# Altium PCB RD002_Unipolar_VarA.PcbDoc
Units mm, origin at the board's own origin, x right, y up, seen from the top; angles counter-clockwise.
Board outline 27 x 14 mm, 4 copper layers (Top Layer, Int1, Int2, Bottom Layer), stack 1.456 mm thick; 29 components, 15 nets, 67 pads, 34 vias.
Unrouted connection lines stored in the file: 1.
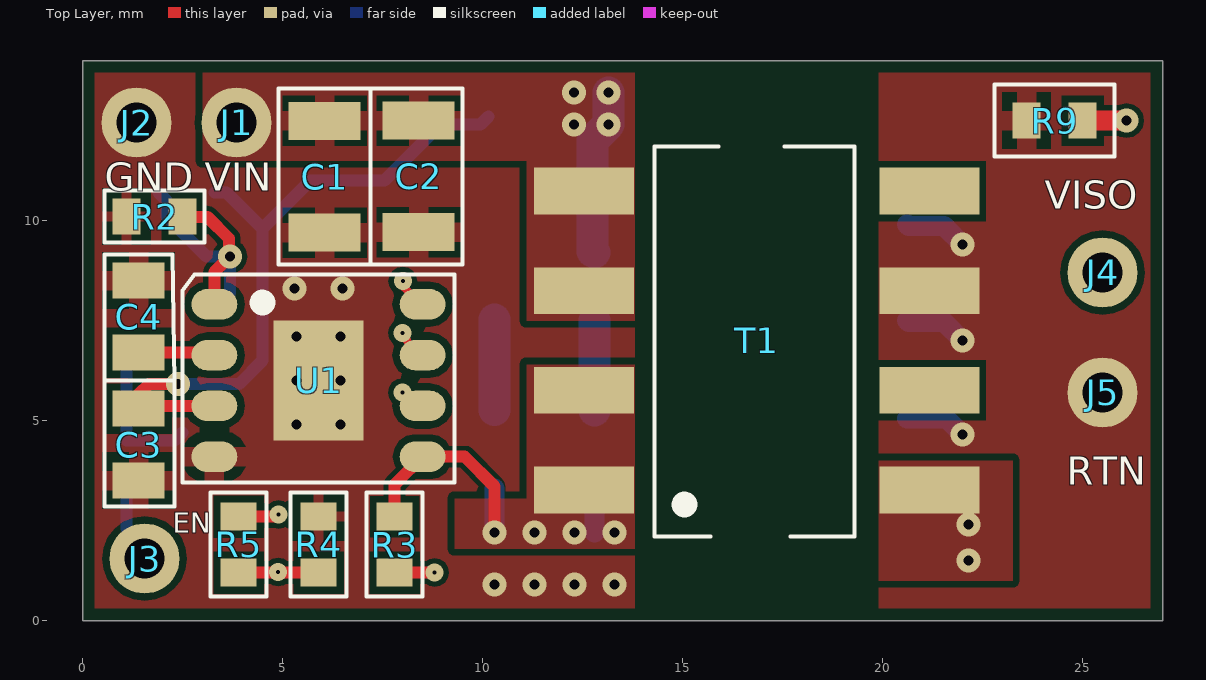
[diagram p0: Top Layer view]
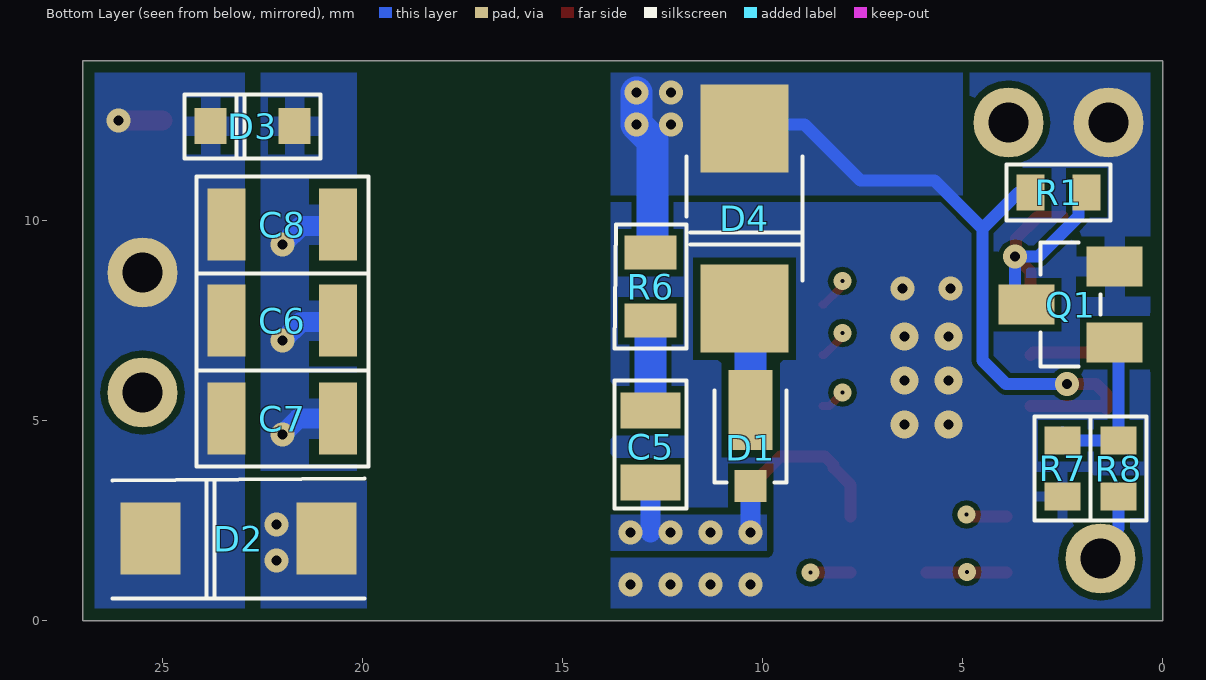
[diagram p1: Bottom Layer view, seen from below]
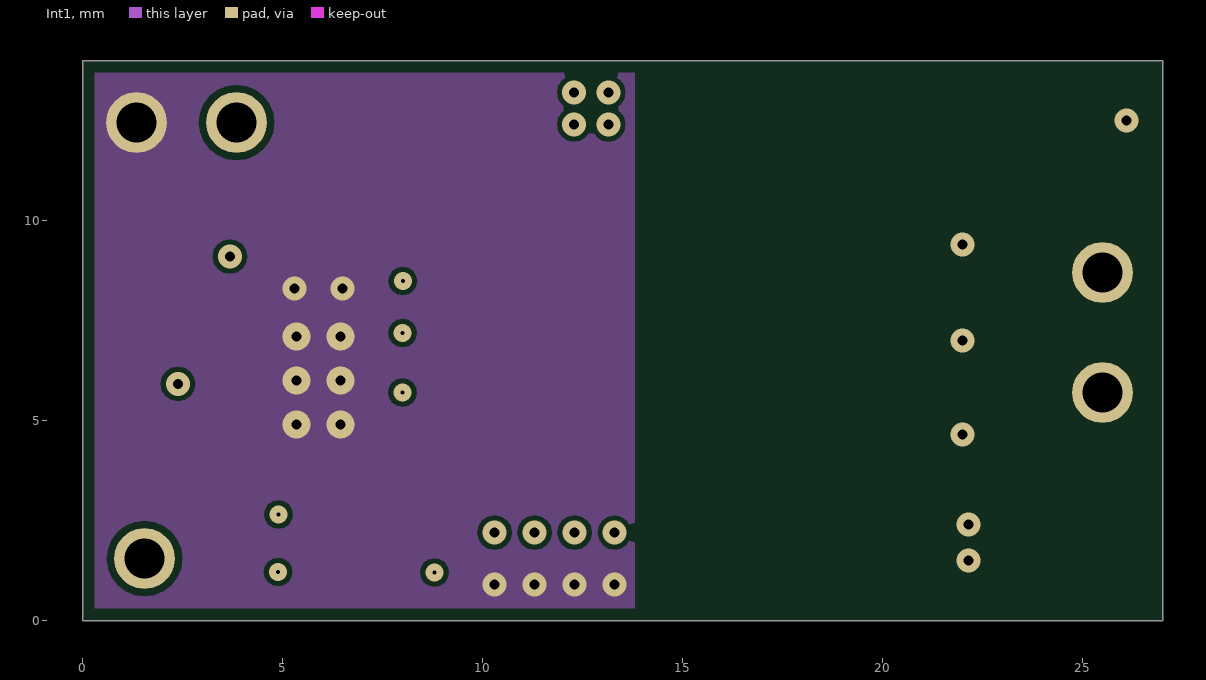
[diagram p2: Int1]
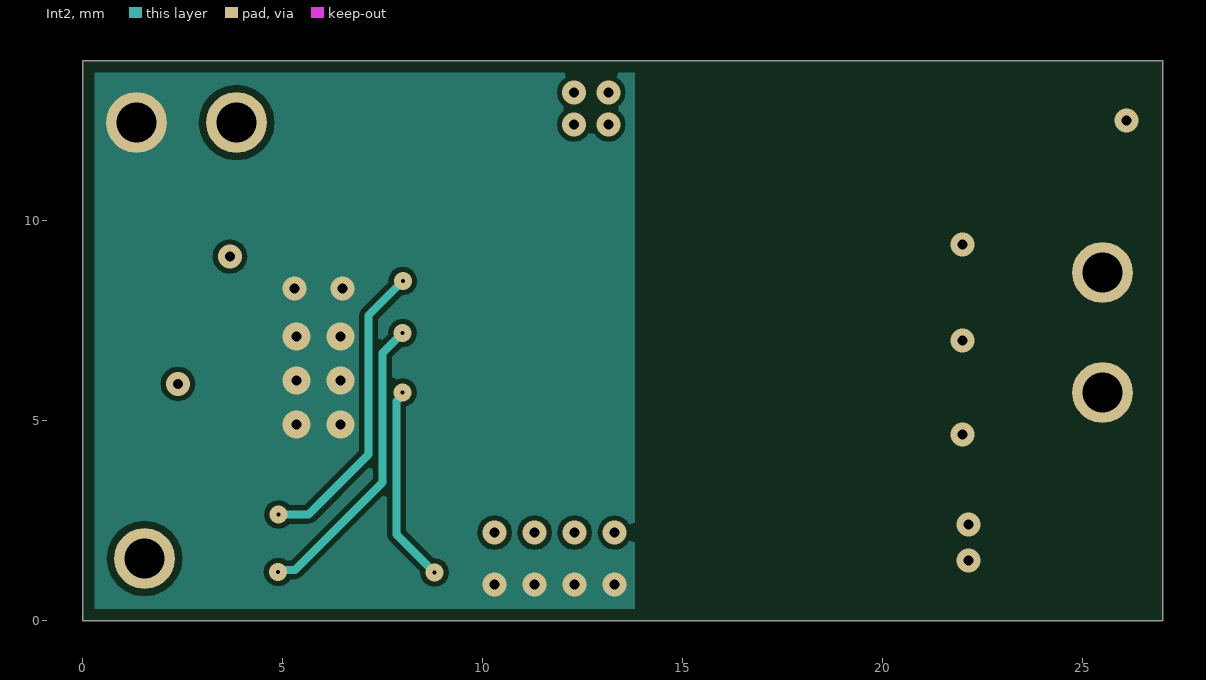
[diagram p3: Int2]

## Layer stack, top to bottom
Top Solder: solder mask 0.0254, SM-001, Dk 4
Top Layer: signal copper 0.035
Dielectric 1: prepreg 0.1067, PP-014, Dk 4.2
Dielectric 2: prepreg 0.1067, PP-014, Dk 4.2
Int1: signal copper 0.035
Dielectric2: core 0.889, Core-041, Dk 4.8
Int2: signal copper 0.0356
Dielectric3: prepreg 0.1067, PP-014, Dk 4.2
Dielectric 3: prepreg 0.1067, PP-014, Dk 4.2
Bottom Layer: signal copper 0.035
Bottom Solder: solder mask 0.0254, SM-001, Dk 4

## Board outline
0,0 27,0 27,14 0,14

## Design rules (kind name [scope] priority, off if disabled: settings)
AcuteAngle [All] p1: minimum=9.00000000000000E+0001 checktracksonly=TRUE
BoardOutlineClearance [All] p1: gap=0.3 ignorepadtopadclearanceinfootprint=FALSE
Clearance Clearance-WE_125um [All] p1: gap=0.175 ignorepadtopadclearanceinfootprint=FALSE except(0.125: Arc-Arc Arc-Track Arc-SMDPad Arc-THPad Arc-Via Arc-Fill Arc-Poly Arc-Region Arc-Text Arc-Hole Track-Track Track-SMDPad Track-THPad Track-Via Track-Fill Track-Poly Track-Region Track-Text Track-Hole Via-Via Via-Fill Via-Poly Via-Region Via-Text Via-Hole)
ComponentClearance [All] p1: gap=0.1 collisioncheckmode=3 verticalgap=0.2 showdistances=FALSE
HoleSize [All] p1: absolutevalues=TRUE maxlimit=10 minlimit=0.02 maxpercent=80.000 minpercent=20.000
HoleToHoleClearance [All] p1: gap=0.6 allowstackedmicrovias=TRUE
MinimumAnnularRing [IsVia] p1: minimumring=0.17
PlaneClearance [All] p1: clearance=0.5
PlaneConnect [All] p1: planeconnectstyle=Relief reliefexpansion=0.508 reliefentries=4 reliefconductorwidth=0.8 reliefairgap=0.254
PolygonConnect PolygonConnect_3 [All vs IsNamedPolygon('VIN_TOP')] p1: connectstyle=Direct reliefconductorwidth=0.254 reliefentries=4 polygonreliefangle="90 Angle" airgapwidth=0.254
PolygonConnect PolygonConnect_2 [All vs IsNamedPolygon('VIN_TOP')] p2: connectstyle=Direct reliefconductorwidth=0.254 reliefentries=4 polygonreliefangle="90 Angle" airgapwidth=0.254
PolygonConnect PolygonConnect_1 [All vs IsNamedPolygon('Top Layer-VIN')] p3: thpad.connectstyle=Relief thpad.reliefconductorwidth=0.254 thpad.reliefentries=4 thpad.polygonreliefangle="90 Angle" thpad.airgapwidth=0.254 smdpad.connectstyle=Direct smdpad.reliefconductorwidth=0.254 smdpad.reliefentries=4 smdpad.polygonreliefangle="90 Angle" smdpad.airgapwidth=0.254 via.connectstyle=Direct via.reliefconductorwidth=0.254 via.reliefentries=4 via.polygonreliefangle="90 Angle" via.airgapwidth=0.254
PolygonConnect [All] p4: connectstyle=Relief reliefconductorwidth=0.5 reliefentries=4 polygonreliefangle="90 Angle" airgapwidth=0.254
RoutingVias [All] p1: holewidth=0.3 width=0.8 viastyle="Through Hole" minholewidth=0.2 minwidth=0.6 maxholewidth=0.4 maxwidth=0.8
SolderMaskExpansion [All] p1: expansion=0.1 istentingtop=FALSE
UnConnectedPin [All] p1:
UnRoutedNet [All] p1: checkbadconnections=TRUE
Width [All] p1: maxlimit=10 minlimit=0.125 preferedwidth=0.3 minimp=50.000000 maximp=50.000000 favimp=50.000000
24 further rules are at their usual default settings.

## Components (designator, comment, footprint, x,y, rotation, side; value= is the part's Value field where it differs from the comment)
C1 "885012108022" C1206 6.05,11.1 r270 top value=10u
C2 "885012108022" C1206 8.4,11.1 r90 top value=10u
C3 "885012207103" C0805#1 1.4,4.4 r90 top value=1u
C4 "885012207103" C0805#1 1.4,7.6 r270 top value=1u
C5 "885012207084" C0805#2 12.8,4.35 r90 bottom value=470p
C6 "885012108022" C1206 22,7.5 r0 bottom value=10u
C7 "885012108022" C1206 22,5.05 r0 bottom value=10u
C8 "885012108022" C1206 22,9.9 r0 bottom value=10u
D1 "V1PM10-M3" D_DO-219AD_(uSMP) 10.3,4.5 r270 bottom
D2 "VSSAF3M10-M3" D_DO-221AC_(SMA_Slim) 23.1,2.05 r0 bottom
D3 "PLZ16BG3H" D_DO-219AC_(uSMF) 22.75,12.35 r0 bottom
D4 "BZG03C27-M3" D_DO-214AC_(SMA) 10.45,10.05 r270 bottom
J1 "Pin_hole_1mm" J_PIN-TH-ROUND-1MM#1 3.85,12.45 r90 top
J2 "Pin_hole_1mm" J_PIN-TH-ROUND-1MM#1 1.35,12.45 r90 top
J3 "Pin_hole_1mm" J_PIN-TH-ROUND-1MM#1 1.55,1.55 r90 top
J4 "Pin_hole_1mm" J_PIN-TH-ROUND-1MM#2 25.75,9.15 r90 top
J5 "Pin_hole_1mm" J_PIN-TH-ROUND-1MM#3 25.8,5.7 r90 top
Q1 "SQ2318AES-T1_BE3" IC_SOT23-3_V 2.3,7.9 r0 bottom
R1 "RC0603FR-07806KL" R0603 2.6,10.7 r0 bottom value=806k
R2 "RC0603FR-07232KL" R0603 1.8,10.1 r0 top value=232k
R3 "RT0603FRE0771K5L" R0603 7.8,1.9 r90 top value=71.5k
R4 "RT0603BRD0710KL" R0603 5.9,1.9 r270 top value=10k
R5 "R0603_DNP" R0603_DNP 3.9,1.9 r270 top value=DNP
R6 "CMP0805-FX-1000ELF" R0805 12.8,8.35 r90 bottom value=100
R7 "RC0603FR-0710KL" R0603 2.5,3.8 r90 bottom value=10k
R8 "RC0603FR-073R3L" R0603 1.1,3.8 r90 bottom value=3.3
R9 "R0603_DNP" R0603_DNP 24.3,12.5 r0 top value=DNP
T1 "750318114" EP7_Extended_Rail 16.85,7 r0 top
U1 "LT8302HS8E#WPBF" LT-S8E-8_V 5.9,6 r0 top

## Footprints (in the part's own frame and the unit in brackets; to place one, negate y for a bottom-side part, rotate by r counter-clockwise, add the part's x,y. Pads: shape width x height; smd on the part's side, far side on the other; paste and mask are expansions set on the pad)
C0805#1 [mm] "Chip Capacitor, 2-Leads, Body 2.00x1.25mm, IPC Low Density"
  rect 0.9x1.3 smd: 1(-0.9,0) 2(0.9,0)
  body extent -1.1,-0.72 1.1,0.72, height 1.45
C0805#2 [mm] "Chip Capacitor, 2-Leads, Body 2.00x1.25mm, IPC Low Density"
  rect 0.9x1.5 smd: 1(-0.9,0) 2(0.9,0)
  body extent -1.1,-0.72 1.1,0.72, height 1.45
C1206 [mm]
  rect 0.95x1.8 smd: 1(-1.39,0) 2(1.4,0)
  body extent -1.7,-0.9 1.7,0.9, height 1.8
D_DO-214AC_(SMA) [mm] "DO-214AC SMA"
  rect 2.2x2.21 smd paste+0 mask+0: A(-2.25,0) C(2.25,0)
  body extent -2.6,-1.28 2.6,1.28, height 2.3
D_DO-219AC_(uSMF) [mm]
  rect 0.8x0.9 smd: A(-1.05,-0.01) C(1.05,-0.01)
  body extent -1.26,-0.66 1.24,0.64, height 0.6
D_DO-219AD_(uSMP) [mil]
  rect 31.5x31.5 smd: A(44.8,0)
  rect 78.74x43.31 smd: C(-30,0)
  body extent -53,-26 45,26, height 29
D_DO-221AC_(SMA_Slim) [mm] "2-Leads, Body 4.2x2.6mm"
  rect 1.5x1.8 smd: A(-2.2,0) C(2.2,0)
  body extent -2.55,-1.3 2.55,1.3, height 1.1
EP7_Extended_Rail [mm] "SMD, 8-Leads, Body 9.8x7.0mm (max), Pitch 2.49mm, IPC Medium Density"
  rect 2.5x1.17 smd: 1(-4.31,-3.735) 2(-4.31,-1.245) 3(-4.31,1.245) 4(-4.31,3.735) 5(4.32,3.735) 6(4.32,1.245) 7(4.32,-1.245) 8(4.32,-3.735)
  body extent -5.06,-5.65 5.04,5.45, height 11.39
IC_SOT23-3_V [mm] "SOT23, 3-Leads, Body 3.12x1.5mm, Pitch 0.95mm"
  rect 1.4x1 smd: 1(-1.1,0.95) 2(-1.1,-0.95) 3(1.1,0)
  body extent -1.35,-1.56 1.35,1.56, height 1.2
J_PIN-TH-ROUND-1MM#1 [mm] "PIN-TH-ROUND-1MM"
  round 1.75 / inner round 1.524 / far side round 1.75 hole 1: 1(0,0)
J_PIN-TH-ROUND-1MM#2 [mm] "PIN-TH-ROUND-1MM"
  round 1.75 / inner round 1.524 / far side round 1.75 hole 1: 1(-0.45,0.25)
J_PIN-TH-ROUND-1MM#3 [mm] "PIN-TH-ROUND-1MM"
  round 1.75 / inner round 1.524 / far side round 1.75 hole 1: 1(0,0.3)
LT-S8E-8_V [mm] "SOIC, 8-Leads, Body 4.9x3.9mm, Pitch 1.27mm, Thermal Pad 3.25x2.26mm, Recommended"
  oval 1.143x0.76 smd: 1(-2.602,1.905) 2(-2.602,0.635) 3(-2.602,-0.635) 4(-2.602,-1.905) 5(2.601,-1.905) 6(2.601,-0.635) 7(2.601,0.635) 8(2.601,1.905)
  rect 2.26x2.99 smd paste-5: 9(0,0)
  body extent -3.01,-2.45 3.01,2.45, height 1.75
R0603 [mm] "Chip Resistor, Body 1.6x0.8mm, IPC High Density"
  rect 0.7x0.9 smd: 1(-0.7,0) 2(0.7,0)
  body extent -0.85,-0.47 0.85,0.47, height 0.6
R0603_DNP [mm] "Chip Resistor, Body 1.6x0.8mm, IPC High Density"
  rect 0.7x0.9 smd: 1(-0.7,0) 2(0.7,0)
R0805 [mm] "Chip Resistor, Body 2.0x1.3mm, IPC High Density"
  rect 0.85x1.3 smd: 1(-0.85,0) 2(0.85,0)
  body extent -1.1,-0.67 1.1,0.68, height 0.7

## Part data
C1 C2 C6 C7 C8: "MLCC 10uF 50V 10% X7R 1206 General Purpose", MFR="Wurth Elektronik", Package=1206, Voltage=50V
C3 C4: "MLCC 1uF 50V 10% X7R 0805 General Purpose", DC-Voltage=50V, Dielectric=X7R, MFR="Wurth Elektronik", Package=0805, Tolerance=10%
C5: "MLCC SMD 470p 50V 10% X7R 0805 General Purpose", MFR="Wurth Elektronik"
D1: "Schottky Rectifier 1A 100V SMD DO-219AD (uSMP) V1PM10-M3", Current=1A, MFR=Vishay, Package="DO-219AD (uSMP)", Voltage=100V
D2: "Schottky Rectifier 3A 100V SMD DO-221AC (SMA_Slim) VSSAF3M10-M3", Current=3A, MFR=Vishay, Package="DO-221AC (SMA Slim)", Voltage=100V
D3: "Zener 16V 0.5W SMD DO-219AC (uSMF) PLZ16BG3H", MFR=Vishay, Package="DO-219AC (uSMF)", Power=0.5W, Voltage=16V
D4: "Zener 27V 3W DO-214AC (SMA) BZG03C27-M3", MFR=Vishay, Package="DO-214AC (SMA)", Power=3W, Voltage=27V
J1 J2 J3 J4 J5: "Pin Hole 1mm"
Q1: "N-Channel MOSFET 40 V SOT23-3", MFR=Vishay
R1: "Thick Film Resistors 806k 1% 0.1W", Case-EIA=0603, Case-Metric=1608, MFR=Yageo, Power="0.1 W", Tolerance="1 %"
R2: "Thick Film Resistors 232k 1% 0.1W", Case-EIA=0603, Case-Metric=1608, MFR=Yageo, Power="0.1 W", Tolerance="1 %"
R3: "Thin Film Resistors 71.5k 0.1% 0.1W 0603 RT0603FRE0771K5L", Case-EIA=0603, Case-Metric=1608, MFR=Yageo, Power="0.1 W", Tolerance="0.1 %"
R4: "Thin Film Resistors 10k 0.1% 0.1W", Case-EIA=0603, Case-Metric=1608, MFR=Yageo, Power="0.1 W", Tolerance="0.1 %"
R5 R9: "Footprint R0603 DNP"
R6: "Thick Film 100 5% 0.5W 0805 High Power CMP0805-FX-1000ELF", Case-EIA=0805, MFR=Bourns, Power="0.5 W", Tolerance="5 %"
R7: "Thick Film Resistors 10k 1% 0.1W", Case-EIA=0603, Case-Metric=1608, MFR=Yageo, Power="0.1 W", Tolerance="1 %"
R8: "Thick Film Resistors 3.3 1% 0.1W", Case-EIA=0603, Case-Metric=1608, MFR=Yageo, Power="0.1 W", Tolerance="1 %"
T1: "WE-AGDT Auxiliary Gate Drive Transformer, EP7, SMT, 9-18Vin, 19Vout, 6W", Input Voltage=9-18V, Interwinding Capacitance=6.8pF, MFR="Wurth Elektronik", Operating Temperature="-40 to +130degC", Output Power=6W, Output Voltage=19V, Switching Frequency=350kHz
U1: "Micropower No-Opto Isolated Flyback Converter, 2.8 to 42 V, -40 to 150 degC, 8-Pin SOIC (S8E), RoHS, AEC-Q100", MFR="Analog Devices / Linear Tech", Output Current="3.6 A", PartNumber=LT8302, Temperature Max="150 degC", Temperature Min="-40 degC"

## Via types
v1: diameter 0.6, hole 0.25, Top Layer to Bottom Layer, 22 vias
v2: diameter 0.45, hole 0.1, Top Layer to Bottom Layer, 6 vias
v3: diameter 0.7, hole 0.25, Top Layer to Bottom Layer, 6 vias

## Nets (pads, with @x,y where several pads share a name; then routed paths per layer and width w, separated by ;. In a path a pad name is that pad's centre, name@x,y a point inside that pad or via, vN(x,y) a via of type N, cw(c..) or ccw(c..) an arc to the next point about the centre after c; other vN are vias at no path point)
D_SNB: D1.C D4.C | length 2.3
  Bottom Layer w0.8: D1.C D4.C@10.3,7.522
EN: J3.1 R8.1 | length 2
  Bottom Layer w0.3: R8.1@1.1,3.3 1.1,2.301 1.173,2.228 1.173,1.677 J3.1@1.45,1.4
EN-Q1: Q1.1 R7.2 R8.2 | length 4
  Bottom Layer w0.3: Q1.1@1.3,6.95 1.1,6.75 R8.2 2.3,4.5 R7.2@2.5,4.7
EN/UVLO: Q1.3 R1.1 R2.2 U1.1 | length 7.2
  Top Layer w0.3: R2.2 2.512,10.088 3.124,10.088 3.667,9.545 3.667,9.116 v1(3.683,9.1) 3.298,8.715 U1.1
  Bottom Layer w0.3: R1.1 2.1,10.5 2.1,10.1 3.1,9.1 v1(3.683,9.1) 3.683,8.183 Q1.3
GND: C1.2 C2.1 C3.1 C4.1 J2.1 Q1.2 R2.1 R4.1 R7.1 U1.4 U1.9
  other v1: 10.3,0.9 11.3,0.9 12.3,0.9 13.3,0.9 5.3,8.3 6.5,8.3
  other v3: 5.35,4.9 6.45,4.9 5.35,6 6.45,6 5.35,7.1 6.45,7.1
GND_ISO: C6.1 C7.1 C8.1 D3.A J5.1 R9.1 T1.6 | length 4.7
  Bottom Layer w0.5: C7.1 21.6,5.05 v1(22,4.65) ; C6.1 20.652,7.458 21.542,7.458 v1(22,7) ; C8.1 20.652,9.858 21.542,9.858 v1(22,9.4)
INTVCC: C4.2 U1.2 | length 1.9
  Top Layer w0.3: C4.2 3.233,6.7 U1.2
R_SNB: C5.2 R6.1 | length 2.3
  Bottom Layer w0.8: C5.2 R6.1
RFB: R3.1 U1.6 | length 6.6
  Top Layer w0.2: v2(8,5.7) 8,5.688 8.323,5.365 U1.6
  Top Layer w0.3: R3.1 v2(8.8,1.2)
  Int2 w0.2: v2(8,5.7) 8,5.632 7.85,5.482 7.85,2.15 v2(8.8,1.2)
RREF: R4.2 R5.2 U1.7 | length 10.3
  Top Layer w0.2: v2(8.002,7.188) 8.002,7.121 8.107,7.016 8.107,6.99 8.462,6.635 U1.7
  Top Layer w0.3: R5.2 R4.2
  Int2 w0.2: v2@4.938,1.263 5.313,1.263 7.5,3.45 7.5,6.686 v2(8.002,7.188)
  Bottom Layer w0.2: v2(4.89,1.215) v2@4.938,1.263
SEC_D2: D2.A T1.8
  other v1: 22.15,1.5 22.15,2.4
SW: C5.1 D1.A R3.2 T1.1 T1.2 U1.5 | length 7.4
  Top Layer w0.3: R3.2 7.8,3.393 8.222,3.815 8.222,3.883 8.434,4.095 U1.5 9.555,4.095 10.3,3.35 v1(10.3,2.2)
  Bottom Layer w0.5: v1(10.3,2.2) D1.A@10.3,3.3 ; 12.8,2.2 C5.1
  other v1: 11.3,2.2 12.3,2.2 13.3,2.2
TC: R5.1 U1.8 | length 9.3
  Top Layer w0.2: v2(8.006,8.487) 8.054,8.439 8.054,8.312 8.462,7.905 U1.8
  Top Layer w0.3: R5.1 v2@4.85,2.6
  Int2 w0.2: v2(4.9,2.65) 5.65,2.65 7.15,4.15 7.15,7.631 v2(8.006,8.487)
V_ISO: C6.2 C7.2 C8.2 D2.C D3.C J4.1 R9.2 | length 1.1
  Top Layer w0.5: R9.2 v1(26.1,12.5)
VIN: C1.1 C2.2 C3.2 D4.A J1.1 R1.2 R6.2 T1.3 T1.4 U1.3 | length 21.8
  Top Layer w0.3: v1@2.35,5.787 2.403,5.84 v1@2.508,5.84 ; v1(2.386,5.914) 1.664,5.914 1.4,5.65 C3.2 1.465,5.365 U1.3
  Bottom Layer w0.3: v1(2.386,5.914) 3.914,5.914 4.5,6.5 4.5,9.8 ; R1.2 3.6,10.7 4.5,9.8 ; D4.A@10.15,12.6 9.95,12.4 8.95,12.4 7.55,11 5.7,11 4.5,9.8
  Bottom Layer w0.8: R6.2 12.775,9.225 12.75,9.225 12.75,12 v1(13.15,12.4) v1(13.15,13.2)
  other v1: 12.283,12.4 12.283,13.2
pads on no net: T1.5 T1.7

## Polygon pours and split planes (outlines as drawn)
GND_ISO on Top Layer "GND_ISO_TOP" (solid, pour order 216): 19.9,0.25 26.75,0.25 26.75,13.75 19.9,13.75
SEC_D2 on Top Layer "GND" (solid, pour order 204): 19.9,1 23.25,1 23.25,4 19.9,4
GND on Top Layer "GND_TOP" (solid, remove dead copper, pour order 184): 13.8,13.75 0.25,13.75 0.25,0.25 13.8,0.25
SW on Top Layer "GND" (solid, remove dead copper, pour order 180): 13.8,6.4 13.8,1.8 9.3,1.8 9.3,3.05 11.1,3.05 11.1,6.4
VIN on Top Layer "VIN_TOP" (solid, remove dead copper, pour order 166): 3,11.5 11.1,11.5 11.1,7.5 13.8,7.5 13.8,13.75 3,13.75
SEC_D2 on Bottom Layer "SEC_D2_BOT" (solid, pour order 214): 19.9,3.5 22.55,3.5 22.55,0.25 19.9,0.25
V_ISO on Bottom Layer "V_ISO_BOT" (solid, pour order 208): 22.95,0.25 26.75,0.25 26.75,13.75 22.95,13.75
GND_ISO on Bottom Layer "GND_ISO_BOT" (solid, pour order 209): 20.15,3.75 22.55,3.75 22.55,13.75 20.15,13.75
SW on Bottom Layer "SW_TOP" (solid, pour order 154): 13.8,1.75 13.8,2.65 9.9,2.65 9.9,1.75
GND on Bottom Layer "GND_BOT" (solid, remove dead copper, pour order 196): 0.25,0.25 13.8,0.25 13.8,13.75 0.25,13.75
VIN on Bottom Layer "VIN_BOT" (solid, remove dead copper, pour order 170): 5,10.632 5,13.75 13.8,13.75 13.8,10.632
GND on Int1 "GND_INT1" (solid, remove dead copper, pour order 198): 0.25,0.25 13.8,0.25 13.8,13.75 0.25,13.75
GND on Int2 "GND_INT2" (solid, remove dead copper, pour order 200): 0.3,0.3 13.8,0.3 13.8,13.7 0.3,13.7

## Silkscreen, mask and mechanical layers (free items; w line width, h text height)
Top Overlay:
  circle w0.5: c15.05,2.9 r0.071
  circle w0.5: c4.5,7.95 r0.071
  lines w0.1: 0.55,5.95 0.55,9.15 2.25,9.15 2.3,5.95 ; 15.7,2.1 14.3,2.1 14.3,11.85 15.9,11.85 ; 17.55,11.85 19.3,11.85 19.3,2.1 17.7,2.1 ; 7.2,8.9 9.5,8.9 9.5,13.3 7.2,13.3 ; 7.2,8.9 7.2,13.3 ; 7.2,8.9 4.9,8.9 4.9,13.3 7.2,13.3 ; 0.55,2.85 0.55,6 2.3,6 2.3,2.85 0.55,2.85 ; 0.55,9.45 0.55,10.75 3.05,10.75 3.05,9.45 0.55,9.45 ; 2.5,3.45 2.5,8.25 2.8,8.65 9.3,8.65 9.3,3.45 2.5,3.45 ; 3.2,0.6 3.2,3.2 4.6,3.2 4.6,0.6 3.2,0.6 ; 5.2,0.6 5.2,3.2 6.6,3.2 6.6,0.6 5.2,0.6 ; 7.1,0.6 7.1,3.2 8.5,3.2 8.5,0.6 7.1,0.6 ; 22.8,11.6 22.8,13.4 25.8,13.4 25.8,11.6 22.8,11.6
  text "GND" at 0.55,10.75 h0.7
  text "VIN" at 3.05,10.75 h0.7
  text "VISO" at 24.05,10.3 h0.7
  text "RTN" at 24.6,3.4 h0.7
  text "EN" at 2.25,2.2 h0.5
Bottom Overlay:
  lines w0.1: 1.55,7.65 1.55,8.15 ; 1.8,2.5 1.8,5.1 ; 2.1,6.35 3.05,6.35 3.05,7.2 ; 2.1,9.45 3.05,9.45 3.05,8.65 ; 9,8.5 9,11.6 ; 9,9.4 11.8,9.4 ; 9,9.7 11.8,9.7 ; 9.4,5.75 9.4,3.45 9.7,3.45 ; 10.9,3.45 11.2,3.45 11.2,5.75 ; 11.9,10.1 11.9,11.6 ; 19.85,8.675 24.15,8.675 ; 19.95,0.55 26.25,0.55 ; 19.95,3.55 26.25,3.5 ; 22.95,11.55 22.95,13.15 ; 23.15,11.55 23.15,13.15 ; 23.7,0.6 23.7,3.5 ; 23.9,0.55 23.9,3.5 ; 1.8,5.1 1.2,5.1 0.4,5.1 0.4,2.5 3.2,2.5 3.2,5.1 1.8,5.1 ; 19.85,6.25 19.85,11.1 24.15,11.1 24.15,6.25 ; 19.85,6.25 19.85,3.85 24.15,3.85 24.15,6.25 ; 19.85,6.25 24.15,6.25 ; 1.3,10 1.3,11.4 3.9,11.4 3.9,10 1.3,10 ; 11.9,2.8 11.9,6 13.7,6 13.7,2.8 11.9,2.8 ; 11.9,6.8 11.9,9.9 13.66,9.9 13.7,6.8 11.9,6.8 ; 21.05,11.55 21.05,13.15 24.45,13.15 24.45,11.55 24.4,11.55 21.05,11.55
Board Outline:
  the board outline again, w0.1
Dimensions:
  text "DIMENSIONS IN MILLIMETER (mm)" at -11,-12 h2
  text "DIMENSIONS" at -30.5,-30.33 h2
Title Sheet:
  drawing of 1620 lines, arcs and shapes, not listed
  text "1" at -56.463,225.931 h1.78
  text "2" at -7.424,225.931 h1.78
  text "3" at 41.835,225.931 h1.78
  text "4" at 91.128,225.931 h1.78
  text "5" at 140.404,225.931 h1.78
  text "6" at 189.426,225.931 h1.78
  text "7" at 238.956,225.931 h1.78
  text "8" at 287.978,225.931 h1.78
  text "Layer" at -56.696,203.994 h1.49
  text "Name" at -46.515,203.994 h1.49
  text "Material" at -13.516,203.994 h1.49
  text "Thickness" at 0.882,203.994 h1.49
  text "Constant" at 17.015,203.994 h1.49
  text "Board Layer Stack" at 31.165,203.994 h1.49
  text "Top Overlay" at -46.515,201.017 h1.49
  text "Top Solder" at -46.515,198.04 h1.49
  text "SM-001" at -13.516,198.04 h1.49
  text "0,025mm" at 2.246,198.04 h1.49
  text "4" at 17.015,198.04 h1.49
  text "Top Surface Finish" at -46.515,195.063 h1.49
  text "PbSn" at -13.516,195.063 h1.49
  text "0,020mm" at 2.246,195.063 h1.49
  text "1" at -56.696,192.086 h1.49
  text "Top Layer" at -46.515,192.086 h1.49
  text "CF-004" at -13.516,192.086 h1.49
  text "0,035mm" at 2.246,192.086 h1.49
  text "A" at -78.595,191.946 h1.78
  text "A" at 310.025,191.946 h1.78
  text "Dielectric 1" at -46.515,189.108 h1.49
  text "PP-014" at -13.516,189.108 h1.49
  text "0,107mm" at 2.37,189.108 h1.49
  text "4.2" at 17.015,189.108 h1.49
  text "Dielectric 2" at -46.515,186.131 h1.49
  text "PP-014" at -13.516,186.131 h1.49
  text "0,107mm" at 2.37,186.131 h1.49
  text "4.2" at 17.015,186.131 h1.49
  text "2" at -56.696,183.154 h1.49
  text "Int1" at -46.515,183.154 h1.49
  text "0,035mm" at 2.246,183.154 h1.49
  text "Dielectric2" at -46.515,180.177 h1.49
  text "Core-041" at -13.516,180.177 h1.49
  text "0,889mm" at 2.246,180.177 h1.49
  text "4.8" at 17.015,180.177 h1.49
  text "3" at -56.696,177.2 h1.49
  text "Int2" at -46.515,177.2 h1.49
  text "0,036mm" at 2.246,177.2 h1.49
  text "Dielectric3" at -46.515,174.223 h1.49
  text "PP-014" at -13.516,174.223 h1.49
  text "0,107mm" at 2.37,174.223 h1.49
  text "4.2" at 17.015,174.223 h1.49
  text "Dielectric 3" at -46.515,171.246 h1.49
  text "PP-014" at -13.516,171.246 h1.49
  text "0,107mm" at 2.37,171.246 h1.49
  text "4.2" at 17.015,171.246 h1.49
  text "4" at -56.696,168.269 h1.49
  text "Bottom Layer" at -46.515,168.269 h1.49
  text "CF-004" at -13.516,168.269 h1.49
  text "0,035mm" at 2.246,168.269 h1.49
  text "Bottom Surface Finish" at -46.515,165.292 h1.49
  text "PbSn" at -13.516,165.292 h1.49
  text "0,020mm" at 2.246,165.292 h1.49
  text "Bottom Solder" at -46.515,162.314 h1.49
  text "SM-001" at -13.516,162.314 h1.49
  text "0,025mm" at 2.246,162.314 h1.49
  text "4" at 17.015,162.314 h1.49
  text "Bottom Overlay" at -46.515,159.337 h1.49
  text "Total board thickness:" at -56.696,156.36 h1.49
  text "1,547mm" at 2.37,156.36 h1.49
  text "B" at -78.595,121.334 h1.78
  text "B" at 310.025,121.334 h1.78
  text "C" at -78.595,50.722 h1.78
  text "C" at 310.025,50.722 h1.78
  text "D" at -78.595,-19.382 h1.78
  text "D" at 310.025,-19.382 h1.78
  text "TITLE:" at 167.5,-28.58 h2
  text "RD002 Unipolar" at 178.5,-28.58 h2
  text "Eleazar Falco" at 182.5,-34.33 h2
  text "ENGINEER:" at 167.5,-34.58 h2
  text "DATE:" at 167.5,-40.68 h2
  text "04/2022" at 179.25,-41.25 h2 r359.59
  text "A" at 180.75,-46.08 h2
  text "REV:" at 200,-46.08 h2
  text "22a" at 207.75,-46.08 h2
  text "N/A" at 247.75,-46.08 h2
  text "VERSION:" at 167.5,-46.18 h2
  text "ASSY VARIANT:" at 225.4,-46.18 h2
  text "1" at -56.463,-50.929 h1.78
  text "2" at -7.424,-50.929 h1.78
  text "3" at 41.835,-50.929 h1.78
  text "4" at 91.128,-50.929 h1.78
  text "5" at 140.404,-50.929 h1.78
  text "6" at 189.426,-50.929 h1.78
  text "7" at 238.956,-50.929 h1.78
  text "8" at 287.978,-50.929 h1.78
Drill Drawing:
  circle w0.254: c-63.181,48.305 r0.847
  lines w0.254: -64.027,39.838 -62.334,39.838 -62.334,41.532 -64.027,41.532 -64.027,39.838 ; -64.027,43.648 -63.181,44.072 -62.334,43.648 -62.757,44.495 -62.334,45.342 -63.181,44.918 -64.027,45.342 -63.604,44.495 -64.027,43.648
  lines w0.381: -65.546,38.695 151.463,38.695 ; -65.546,50.125 151.463,50.125 ; -51.554,34.885 -51.554,53.935 ; -37.841,34.885 -37.841,53.935 ; -9.655,34.885 -9.655,53.935 ; 3.194,34.885 3.194,53.935 ; 21.832,34.885 21.832,53.935 ; 59.921,34.885 59.921,53.935 ; 74.903,34.885 74.903,53.935 ; 93.846,34.885 93.846,53.935 ; 115.837,34.885 115.837,53.935 ; -65.546,34.885 151.463,34.885 151.463,53.935 -65.546,53.935 -65.546,34.885
  text "Symbol" at -63.26,51.268 h1.83
  text "Count" at -50.411,51.268 h1.83
  text "Hole Size" at -36.698,51.268 h1.83
  text "Plated" at -8.512,51.268 h1.83
  text "Hole Type" at 4.337,51.268 h1.83
  text "Drill Layer Pair" at 22.975,51.268 h1.83
  text "Via/Pad" at 61.064,51.268 h1.83
  text "Pad Shape" at 76.046,51.268 h1.83
  text "Hole Length" at 94.989,51.268 h1.83
  text "Routed Path Length" at 116.98,51.268 h1.83
  text "6" at -50.411,47.458 h1.52
  text "0,100mm (3,94mil)" at -36.698,47.458 h1.52
  text "PTH" at -8.512,47.458 h1.52
  text "Round" at 4.337,47.458 h1.52
  text "Top Layer - Bottom Layer" at 22.975,47.458 h1.52
  text "Via" at 61.064,47.458 h1.52
  text "Rounded" at 76.046,47.458 h1.52
  text "-" at 94.989,47.458 h1.52
  text "-" at 116.98,47.458 h1.52
  text "28" at -50.411,43.648 h1.52
  text "0,250mm (9,84mil)" at -36.698,43.648 h1.52
  text "PTH" at -8.512,43.648 h1.52
  text "Round" at 4.337,43.648 h1.52
  text "Top Layer - Bottom Layer" at 22.975,43.648 h1.52
  text "Via" at 61.064,43.648 h1.52
  text "Rounded" at 76.046,43.648 h1.52
  text "-" at 94.989,43.648 h1.52
  text "-" at 116.98,43.648 h1.52
  text "5" at -50.411,39.838 h1.52
  text "1,000mm (39,37mil)" at -36.698,39.838 h1.52
  text "PTH" at -8.512,39.838 h1.52
  text "Round" at 4.337,39.838 h1.52
  text "Top Layer - Bottom Layer" at 22.975,39.838 h1.52
  text "Pad" at 61.064,39.838 h1.52
  text "Rounded" at 76.046,39.838 h1.52
  text "-" at 94.989,39.838 h1.52
  text "-" at 116.98,39.838 h1.52
  text "39 Total" at -50.411,36.028 h1.52
  text "DRILL Guide" at -27.5,-30.33 h2
Gerber Print:
  drawing of 1652 lines, arcs and shapes, not listed
  text "ARTWORK VIEWED FROM TOP SIDE OF BOARD" at -34.25,-22.08 h1.6
  text "BOARD NAME:" at -44.5,-26.33 h2
  text "RD002 Unipolar" at -21.5,-26.33 h2
  text "LAYER:" at -44.5,-30.58 h2
  text "SCALE:" at 16.5,-34.58 h2
  text "2:1" at 29.5,-34.58 h2
  text "REV:" at -4.3,-34.8 h2
  text "VERSION:" at -44.5,-34.83 h2
  text "A (2S-4L)" at -28,-34.83 h2
  text "22a" at 3.8,-34.85 h2
  text "GENERATED:" at -44.5,-39.08 h2
  text "04/2022" at -21.5,-39.08 h2
  text "(c) Wurth Elektronik eiSos Group        www.we-online.de" at -45.5,-43.58 h2
Assembly Notes:
  lines w0.1: 181.25,22.92 298.25,22.92 ; 181.25,30.92 298.25,30.92 ; 181.25,46.92 298.25,46.92 298.25,79.92 181.25,79.92 181.25,93.92 ; 181.25,122.92 298.25,122.92 ; 181.25,139.92 298.25,139.92 ; 181.25,158.92 298.25,158.92 ; 181.33,4.67 298.33,4.67 ; 186.25,-11.08 291.25,-11.08 ; 186.25,-4.08 291.25,-4.08 ; 218.25,177.92 231.25,177.92 ; 218.25,185.92 231.25,185.92 ; 238.6,165.32 251.6,165.32 ; 273.25,66.92 291.25,66.92 ; 273.25,82.92 291.25,82.92 ; 273.25,90.92 291.25,90.92 ; 273.25,108.92 291.25,108.92 ; 275.25,177.92 288.25,177.92 ; 275.25,185.92 288.25,185.92 ; 181.25,-17.08 298.25,-17.08 298.25,212.92 193.25,212.92 181.25,212.92 181.25,-17.08 ; 181.25,104.92 298.25,104.92 181.25,104.92 ; 181.25,200.92 298.25,200.92 181.25,200.92 ; 189.25,34.92 192.25,34.92 192.25,37.92 189.25,37.92 189.25,34.92 ; 189.25,67.92 192.25,67.92 192.25,70.92 189.25,70.92 189.25,67.92 ; 189.25,91.92 192.25,91.92 192.25,94.92 189.25,94.92 189.25,91.92 ; 189.25,108.92 192.25,108.92 192.25,111.92 189.25,111.92 189.25,108.92 ; 207.25,67.92 210.25,67.92 210.25,70.92 207.25,70.92 207.25,67.92 ; 213.25,83.92 216.25,83.92 216.25,86.92 213.25,86.92 213.25,83.92 ; 213.25,91.92 216.25,91.92 216.25,94.92 213.25,94.92 213.25,91.92 ; 213.25,108.92 216.25,108.92 216.25,111.92 213.25,111.92 213.25,108.92 ; 217.25,142.92 220.25,142.92 220.25,145.92 217.25,145.92 217.25,142.92 ; 217.25,147.92 220.25,147.92 220.25,150.92 217.25,150.92 217.25,147.92 ; 217.25,152.92 220.25,152.92 220.25,155.92 217.25,155.92 217.25,152.92 ; 220.25,34.92 223.25,34.92 223.25,37.92 220.25,37.92 220.25,34.92 ; 237.25,66.92 240.25,66.92 240.25,69.92 237.25,69.92 237.25,66.92 ; 238.25,83.92 241.25,83.92 241.25,86.92 238.25,86.92 238.25,83.92 ; 238.25,91.92 241.25,91.92 241.25,94.92 238.25,94.92 238.25,91.92 ; 238.25,108.92 241.25,108.92 241.25,111.92 238.25,111.92 238.25,108.92 ; 250.25,34.92 253.25,34.92 253.25,37.92 250.25,37.92 250.25,34.92 ; 253.25,25.92 256.25,25.92 256.25,28.92 253.25,28.92 253.25,25.92 ; 254.25,145.92 257.25,145.92 257.25,148.92 254.25,148.92 254.25,145.92 ; 254.25,149.92 257.25,149.92 257.25,152.92 254.25,152.92 254.25,149.92 ; 271.25,25.92 274.25,25.92 274.25,28.92 271.25,28.92 271.25,25.92
  text "FABRICATION NOTES" at 214.55,204.92 h3
  text "MINIMUM SIZE CONSTRAINTS" at 215.25,194.92 h2
  text "TRACK WIDTH (MIN):" at 184.25,186.92 h2
  text "0.2  mm" at 222.25,186.92 h2
  text "CLEARANCE (MIN):" at 244.25,186.92 h2
  text "0.125 mm" at 277.8,186.9 h2
  text "DRILL DIAM.(MIN):" at 184.25,178.92 h2
  text "0.1  mm" at 222.25,178.92 h2
  text "PAD SIZE (MIN):" at 244.25,178.92 h2
  text "XXXX mm" at 279.25,178.92 h2
  text "ANNULAR RING DIAMETER (MIN):" at 184.25,166.92 h2
  text "0.45 mm" at 242.6,166.32 h2
  text "VIAS DETAILS:" at 184.25,153.92 h2
  text "VIAS IN PAD" at 222.25,152.92 h2
  text "CONDUCTIVE FILL" at 259.25,149.92 h2
  text "TENTED VIAS" at 222.25,147.92 h2
  text "NON-CONDUCTIVE FILL" at 259.25,145.92 h2
  text "FILLED VIAS" at 222.25,142.92 h2
  text "FURTHER VIA DETAILS IN DRAWING ATTACHED" at 184.25,133.92 h2
  text "DRILL AND HOLES DETAILS SEE ADJACENT TABLE" at 184.25,129.92 h2
  text "SUBSTRATE MATERIAL AND LAYER STACK-UP SEE ADJACENT TABLE" at 184.25,125.92 h2
  text "SURFACE FINISH PLATING" at 184.25,117.92 h2
  text "ENIG" at 194.25,109.92 h2
  text "ImAg" at 218.75,109.92 h2
  text "ImSn" at 243.25,109.92 h2
  text "OTHER:" at 261.25,109.92 h2
  text "SOLDER MASK COLOR:" at 184.25,99.92 h2
  text "x" at 190.05,92.72 h2
  text "RED" at 194.25,91.92 h2
  text "GREEN" at 218.75,91.92 h2
  text "BLUE" at 243.25,91.92 h2
  text "OTHER:" at 261.25,91.92 h2
  text "x" at 239.1,84.62 h2
  text "FINISH:" at 190.25,83.92 h2
  text "MATTE" at 218.75,83.92 h2
  text "GLOSS" at 243.25,83.92 h2
  text "OTHER:" at 261.25,83.92 h2
  text "SILKSCREEN:" at 197.25,74.92 h2
  text "SILKSCREEN COLOR:" at 241.25,74.92 h2
  text "x" at 190.15,68.82 h2
  text "x" at 208.15,68.82 h2
  text "TOP" at 194.25,67.92 h2
  text "BOTTOM" at 212.25,67.92 h2
  text "WHITE" at 242.25,67.92 h2
  text "OTHER:" at 261.25,67.92 h2
  text "x" at 238.05,67.72 h2
  text "NOTES:" at 192.25,58.92 h2
  text "SILKSCREEN LOCATION AS PER GERBER FILE XXX" at 207.25,58.92 h2
  text "NO SILKSCREEN ON EXPOSED CONDUCTIVE PADS" at 207.25,54.92 h2
  text "USE PERMANENT NON-CONDUCTIVE INK" at 207.25,50.92 h2
  text "ARRAY-PANELIZATION CUT-OUT" at 214.25,41.92 h2
  text "x" at 251.2,35.7 h2
  text "V-SCORE" at 194.25,34.92 h2
  text "NC-ROUTE" at 225.25,34.92 h2
  text "LOOSE (CUT AND TRIM)" at 255.25,34.92 h2
  text "x" at 254.05,26.72 h2
  text "ELECTRICAL TEST REQUIRED:" at 184.25,25.92 h2
  text "YES" at 258.25,25.92 h2
  text "NO" at 276.25,25.92 h2
  text "ADDITIONAL REQUIREMENTS NOT SPECIFIED SHALL MEET OR EXCEED IPC-6012 CLASS-B SPECIFICATION" at 184,15.342 h2 r0.04
  text "ACCEPTANCE CRITERIA AS PER IPC-600 CLASS B" at 184.25,12.42 h2
  text "RoHS COMPLIANCE" at 184.5,9.42 h2
  text "ADDITIONAL INFORMATION:" at 188.5,0.42 h2
Top_Print_Gerber:
  text "TOP Route" at -30.5,-30.58 h2
Int1_Print_Gerber:
  text "INT1 Layer Route" at -30.5,-30.58 h2
Int2_Print_Gerber:
  text "INT2 Layer Route" at -29.5,-30.58 h2
Bottom_Print_Gerber:
  text "BOTTOM Route" at -30.5,-30.58 h2
TopPaste_Print_Gerber:
  text "TOP Paste" at -30.5,-30.58 h2
BottomPaste_Print_Gerber:
  text "BOTTOM Paste" at -30.5,-30.58 h2
TopSolder_Print_Gerber:
  text "TOP Soldermask" at -30.5,-30.58 h2
BottomSolder_Print_Gerber:
  text "BOTTOM Soldermask" at -30.5,-30.58 h2
Top_Reference_Print_Gerber:
  text "TOP Assembly Reference" at -30.5,-30.58 h2
Top_Silkscreen_Print_Gerber:
  text "TOP Silkscreen" at -30.5,-30.33 h2
Bottom_Silkscreen_Print_Gerber:
  text "BOTTOM Silkscreen" at -30.5,-30.58 h2
Bottom_Reference_Print_Gerber:
  text "BOTTOM Assembly Reference" at -30.5,-30.58 h2

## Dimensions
0,0 to 0,14 on Dimensions
0,0 to 27,0 on Dimensions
